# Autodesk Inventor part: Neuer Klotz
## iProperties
Created: 2006-11
Part Number: Neuer Klotz
Cost Center: 0,283 kg
Material: Messing (gelb, weich)
Document SubType Name: Modeling
Designer: Schmidt
Authority: 104350 mm^3
Density: 8.47 g/cm^3
SaveDate: 2006-11-03
SaveTime: 00:38
TotalMass: 0,283 kg
TotalVolume: 104350 mm^3
Author: Schmidt
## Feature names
1. Extrusion2
2. Extrusion3
3. Bohrung2 [Hole]
4. Rechteckige Anordnung1 [Rectangular Pattern]
5. Extrusion4
